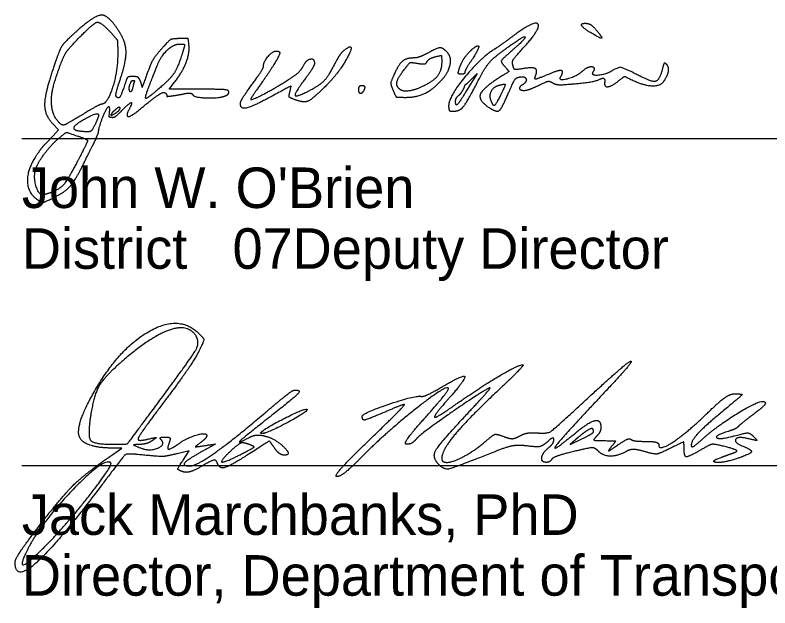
# Model space of a CAD drawing. Extents: x -1.1 to 34, y 0 to 29.8.
# Drawn here: x 24.632 to 27.241, y 6.685 to 8.733 of the extents above; entities that cross this region are included whole.
import ezdxf

# ---------------------------------------------------------------- set-up
doc = ezdxf.new("R2010")
doc.units = 0
doc.layers.add('SH_Data', color=7, linetype='Continuous')
doc.layers.add('SH_Text', color=7, linetype='Continuous')

msp = doc.modelspace()

# ---------------------------------------------------------------- linework, layer by layer
at = {"layer": 'SH_Data'}
for p, q in [((24.6551, 8.3067), (28.1551, 8.3067)), ((24.6551, 7.1773), (28.1551, 7.1773))]:
    msp.add_line(p, q, dxfattribs=at)
at = {"layer": 'SH_Text'}
for p, q in [((26.6204, 8.673), (26.6204, 8.673)), ((25.1173, 7.3823), (25.1173, 7.3823)), ((25.4827, 7.2925), (25.4827, 7.2925)), ((26.6316, 7.2945), (26.6316, 7.2945)), ((25.8545, 7.2635), (25.8545, 7.2635)), ((25.4379, 7.2508), (25.4379, 7.2508))]:
    msp.add_line(p, q, dxfattribs=at)
for points in [[(26.7632, 8.537), (26.7242, 8.5536), (26.7012, 8.5451)], [(26.1956, 8.4978), (26.229, 8.531), (26.1944, 8.4761)], [(25.2675, 8.4771), (25.1647, 8.4771), (25.183, 8.5011)], [(24.7618, 8.3577), (24.7812, 8.3371), (24.7618, 8.3153)], [(26.5799, 7.2748), (26.5504, 7.2492), (26.591, 7.2689)], [(24.9697, 7.2154), (25.0004, 7.2366), (24.9625, 7.2373)], [(25.2126, 7.1956), (25.2338, 7.2279), (25.1921, 7.2178)]]:
    msp.add_lwpolyline(points, dxfattribs=at)
for points in [[(24.9948, 8.6707), (24.9576, 8.7316), (24.9082, 8.7347), (24.8471, 8.68)], [(24.8491, 8.6511), (24.9029, 8.7064), (24.9271, 8.7109), (24.9632, 8.6723)], [(26.3801, 8.6107), (26.4497, 8.6855), (26.4295, 8.7184), (26.3504, 8.659)], [(26.6204, 8.673), (26.5942, 8.689), (26.586, 8.7053), (26.6044, 8.7049)], [(26.6044, 8.7049), (26.6159, 8.7046), (26.6335, 8.6913), (26.6494, 8.6711)], [(24.8471, 8.68), (24.8009, 8.6387), (24.7832, 8.6097), (24.7591, 8.5362)], [(24.9632, 8.6723), (24.9836, 8.6504), (24.9864, 8.6415), (24.9864, 8.5982)], [(24.9935, 8.5062), (25.0151, 8.5702), (25.0156, 8.6364), (24.9948, 8.6707)], [(26.6494, 8.6711), (26.6638, 8.6527), (26.6526, 8.6534), (26.6204, 8.673)], [(24.7866, 8.5571), (24.7992, 8.5912), (24.8172, 8.6184), (24.8491, 8.6511)], [(25.1995, 8.6521), (25.1737, 8.6513), (25.1635, 8.6454), (25.1377, 8.6163)], [(25.2328, 8.6287), (25.2306, 8.6515), (25.2284, 8.653), (25.1995, 8.6521)], [(26.2439, 8.5279), (26.2609, 8.5605), (26.3003, 8.5985), (26.3604, 8.6402)], [(26.3504, 8.659), (26.3284, 8.6425), (26.2996, 8.6221), (26.2864, 8.6136)], [(26.3604, 8.6402), (26.396, 8.6648), (26.3932, 8.6487), (26.3564, 8.6167)], [(25.1377, 8.6163), (25.1208, 8.5972), (25.1032, 8.5716), (25.0986, 8.5593)], [(25.1227, 8.5582), (25.1352, 8.5904), (25.1792, 8.6331), (25.1998, 8.6331)], [(25.214, 8.6151), (25.1971, 8.5593), (25.1726, 8.5174), (25.1402, 8.4888)], [(25.183, 8.5011), (25.2105, 8.5373), (25.2355, 8.6012), (25.2328, 8.6287)], [(25.1998, 8.6331), (25.2165, 8.6331), (25.2187, 8.6304), (25.214, 8.6151)], [(25.7671, 8.6097), (25.81, 8.6453), (25.7561, 8.5389), (25.7059, 8.4887)], [(26.1248, 8.6055), (26.1092, 8.6212), (26.0917, 8.6201), (26.0563, 8.6011)], [(26.2864, 8.6136), (26.2365, 8.5816), (26.1304, 8.4497), (26.1304, 8.4197)], [(26.1669, 8.5471), (26.1734, 8.5679), (26.1964, 8.6021), (26.2133, 8.6162)], [(26.2133, 8.6162), (26.2353, 8.6344), (26.2333, 8.6125), (26.2098, 8.5776)], [(26.3564, 8.6167), (26.3151, 8.5808), (26.3104, 8.5708), (26.3264, 8.5532)], [(24.9864, 8.5982), (24.9864, 8.5383), (24.9497, 8.4251), (24.9302, 8.4251)], [(25.5464, 8.6019), (25.5464, 8.5941), (25.5058, 8.5292), (25.467, 8.4751)], [(25.4904, 8.5571), (25.4904, 8.5721), (25.5221, 8.6091), (25.535, 8.6091)], [(25.535, 8.6091), (25.5413, 8.6091), (25.5464, 8.6059), (25.5464, 8.6019)], [(25.7382, 8.5666), (25.7477, 8.585), (25.7607, 8.6044), (25.7671, 8.6097)], [(26.0102, 8.5851), (25.9842, 8.5851), (25.9578, 8.5633), (25.9425, 8.5292)], [(26.0563, 8.6011), (26.0399, 8.5923), (26.0191, 8.5851), (26.0102, 8.5851)], [(26.0563, 8.573), (26.0597, 8.579), (26.0723, 8.5863), (26.0844, 8.5893)], [(26.0844, 8.5893), (26.1048, 8.5944), (26.1064, 8.593), (26.1064, 8.5706)], [(26.1058, 8.5085), (26.13, 8.5342), (26.1409, 8.5895), (26.1248, 8.6055)], [(26.3524, 8.5599), (26.3494, 8.5716), (26.3573, 8.5862), (26.3801, 8.6107)], [(25.0986, 8.5593), (25.0699, 8.4818), (25.0721, 8.4855), (25.0652, 8.504)], [(25.6279, 8.5571), (25.6373, 8.5779), (25.6664, 8.585), (25.6664, 8.5666)], [(25.6664, 8.5666), (25.6664, 8.5607), (25.652, 8.5367), (25.6343, 8.513)], [(25.6475, 8.4717), (25.6856, 8.4913), (25.7156, 8.5227), (25.7382, 8.5666)], [(25.9755, 8.5432), (25.994, 8.5675), (25.9998, 8.5703), (26.0234, 8.5665)], [(26.0234, 8.5665), (26.0414, 8.5636), (26.0522, 8.5657), (26.0563, 8.573)], [(26.1064, 8.5706), (26.1064, 8.5411), (26.0769, 8.5039), (26.0393, 8.4861)], [(26.2098, 8.5776), (26.1969, 8.5584), (26.1864, 8.5396), (26.1864, 8.5359)], [(26.3856, 8.548), (26.3611, 8.5441), (26.3561, 8.5459), (26.3524, 8.5599)], [(26.8839, 8.5629), (26.8778, 8.5689), (26.8736, 8.5647), (26.8696, 8.5483)], [(26.8748, 8.5051), (26.8883, 8.526), (26.8927, 8.554), (26.8839, 8.5629)], [(24.7591, 8.5362), (24.7331, 8.4569), (24.7342, 8.3872), (24.7618, 8.3577)], [(24.76, 8.4077), (24.7544, 8.437), (24.7656, 8.4997), (24.7866, 8.5571)], [(25.0993, 8.4991), (25.1085, 8.5222), (25.119, 8.5488), (25.1227, 8.5582)], [(25.4504, 8.4931), (25.4724, 8.5229), (25.4904, 8.5517), (25.4904, 8.5571)], [(25.5766, 8.5102), (25.5998, 8.525), (25.6229, 8.5461), (25.6279, 8.5571)], [(25.9597, 8.4784), (25.9486, 8.4896), (25.9552, 8.5166), (25.9755, 8.5432)], [(26.1739, 8.5291), (26.1645, 8.5291), (26.1628, 8.5337), (26.1669, 8.5471)], [(26.1864, 8.5359), (26.1864, 8.5322), (26.1808, 8.5291), (26.1739, 8.5291)], [(26.3264, 8.5532), (26.339, 8.5392), (26.3385, 8.5376), (26.3171, 8.5243)], [(26.4316, 8.5254), (26.4388, 8.5441), (26.4197, 8.5534), (26.3856, 8.548)], [(26.4882, 8.5336), (26.4363, 8.5124), (26.426, 8.5109), (26.4316, 8.5254)], [(26.5177, 8.52), (26.5286, 8.5377), (26.5144, 8.5443), (26.4882, 8.5336)], [(26.592, 8.5388), (26.5725, 8.5206), (26.508, 8.5043), (26.5177, 8.52)], [(26.6304, 8.5372), (26.6406, 8.5536), (26.6093, 8.5549), (26.592, 8.5388)], [(26.7012, 8.5451), (26.6797, 8.5287), (26.6213, 8.5224), (26.6304, 8.5372)], [(26.8696, 8.5483), (26.8591, 8.5054), (26.828, 8.5021), (26.7632, 8.537)], [(25.0393, 8.5211), (25.0236, 8.5211), (25.0177, 8.515), (25.0101, 8.4911)], [(25.0334, 8.5051), (25.0469, 8.5117), (25.0402, 8.4926), (25.039, 8.4848)], [(25.0652, 8.504), (25.0611, 8.5151), (25.052, 8.5211), (25.0393, 8.5211)], [(25.4468, 8.4411), (25.455, 8.4411), (25.5353, 8.4838), (25.5766, 8.5102)], [(25.6343, 8.513), (25.5972, 8.4632), (25.6019, 8.4483), (25.6475, 8.4717)], [(25.9425, 8.5292), (25.9304, 8.5024), (25.9297, 8.494), (25.9383, 8.4734)], [(25.9824, 8.4491), (26.0198, 8.4491), (26.075, 8.4757), (26.1058, 8.5085)], [(26.145, 8.4011), (26.1696, 8.4011), (26.1947, 8.4333), (26.2439, 8.5279)], [(26.3171, 8.5243), (26.2496, 8.4824), (26.2313, 8.4394), (26.2701, 8.414)], [(26.3352, 8.4592), (26.3537, 8.5026), (26.3643, 8.5178), (26.3772, 8.5197)], [(26.3772, 8.5197), (26.3951, 8.5223), (26.4019, 8.5027), (26.3864, 8.4931)], [(26.5835, 8.4976), (26.6355, 8.5025), (26.6741, 8.5221), (26.6691, 8.4972)], [(26.7172, 8.5056), (26.7376, 8.5216), (26.7387, 8.5217), (26.7682, 8.5076)], [(26.7682, 8.5076), (26.8056, 8.4898), (26.8639, 8.4884), (26.8748, 8.5051)], [(24.9817, 8.4512), (24.9789, 8.454), (24.9842, 8.4787), (24.9935, 8.5062)], [(25.0101, 8.4911), (24.9994, 8.4578), (24.9893, 8.4436), (24.9817, 8.4512)], [(25.0264, 8.4806), (25.0264, 8.4848), (25.027, 8.4904), (25.0334, 8.5051)], [(25.039, 8.4848), (25.035, 8.4675), (25.0264, 8.4691), (25.0264, 8.4806)], [(25.1402, 8.4888), (25.0892, 8.444), (25.0785, 8.4467), (25.0993, 8.4991)], [(25.4104, 8.428), (25.4104, 8.434), (25.4284, 8.4633), (25.4504, 8.4931)], [(25.5818, 8.4694), (25.5866, 8.4889), (25.585, 8.4885), (25.5199, 8.4533)], [(25.7059, 8.4887), (25.66, 8.4429), (25.6295, 8.4293), (25.599, 8.4409)], [(25.8311, 8.4891), (25.8241, 8.4891), (25.8184, 8.4834), (25.8184, 8.4764)], [(25.8406, 8.4796), (25.8423, 8.4848), (25.838, 8.4891), (25.8311, 8.4891)], [(26.0393, 8.4861), (26.0114, 8.4729), (25.9694, 8.4688), (25.9597, 8.4784)], [(26.1817, 8.4772), (26.1855, 8.4839), (26.1862, 8.4927), (26.1956, 8.4978)], [(26.2771, 8.4376), (26.2701, 8.4558), (26.2864, 8.4862), (26.3057, 8.4912)], [(26.3057, 8.4912), (26.326, 8.4966), (26.3265, 8.49), (26.3084, 8.4536)], [(26.3864, 8.4931), (26.3738, 8.4853), (26.3771, 8.4731), (26.3919, 8.4731)], [(26.3919, 8.4731), (26.3993, 8.4731), (26.4214, 8.4809), (26.441, 8.4904)], [(26.441, 8.4904), (26.4685, 8.5037), (26.4798, 8.5056), (26.4906, 8.4989)], [(26.4906, 8.4989), (26.5003, 8.4928), (26.5282, 8.4924), (26.5835, 8.4976)], [(26.6691, 8.4972), (26.6695, 8.4839), (26.6949, 8.488), (26.7172, 8.5056)], [(25.0595, 8.4048), (25.0935, 8.4334), (25.1535, 8.4776), (25.1567, 8.4523)], [(25.1567, 8.4523), (25.1708, 8.4536), (25.1955, 8.4574), (25.2115, 8.4606)], [(25.2115, 8.4606), (25.23, 8.4644), (25.2425, 8.4634), (25.246, 8.4578)], [(25.246, 8.4578), (25.2516, 8.4486), (25.3362, 8.4457), (25.3577, 8.454)], [(25.3704, 8.468), (25.3704, 8.4743), (25.3394, 8.4771), (25.2675, 8.4771)], [(25.3577, 8.454), (25.3647, 8.4566), (25.3704, 8.4629), (25.3704, 8.468)], [(25.467, 8.4751), (25.4536, 8.4564), (25.4445, 8.4411), (25.4468, 8.4411)], [(25.599, 8.4409), (25.5804, 8.4479), (25.5776, 8.4527), (25.5818, 8.4694)], [(25.8184, 8.4764), (25.8184, 8.4623), (25.8356, 8.4648), (25.8406, 8.4796)], [(25.9383, 8.4734), (25.9473, 8.4517), (25.952, 8.4491), (25.9824, 8.4491)], [(26.1944, 8.4761), (26.1682, 8.4321), (26.1544, 8.4178), (26.1544, 8.4344)], [(26.1544, 8.4344), (26.1544, 8.4414), (26.1598, 8.4516), (26.1664, 8.4571)], [(26.1664, 8.4571), (26.173, 8.4626), (26.1784, 8.4719), (26.1817, 8.4772)], [(26.3001, 8.4012), (26.3058, 8.4013), (26.3215, 8.4274), (26.3352, 8.4592)], [(24.998, 8.4007), (25.0244, 8.4283), (25.0391, 8.4329), (25.0267, 8.4096)], [(25.5199, 8.4533), (25.453, 8.417), (25.4104, 8.4072), (25.4104, 8.428)], [(26.3084, 8.4536), (26.2931, 8.4228), (26.2845, 8.4184), (26.2771, 8.4376)], [(24.7997, 8.3531), (24.7891, 8.3531), (24.7637, 8.3879), (24.76, 8.4077)], [(24.9302, 8.4251), (24.9262, 8.4251), (24.8963, 8.4089), (24.8637, 8.3891)], [(24.9192, 8.3249), (24.9222, 8.3539), (24.9632, 8.4433), (24.9555, 8.3826)], [(24.9681, 8.3962), (24.9708, 8.4), (24.9754, 8.404), (24.9816, 8.4091)], [(24.9816, 8.4091), (24.9918, 8.4194), (24.995, 8.4085), (24.9874, 8.4005)], [(25.0267, 8.4096), (25.0131, 8.3843), (25.0319, 8.3816), (25.0595, 8.4048)], [(26.1304, 8.4197), (26.1304, 8.407), (26.1351, 8.4011), (26.145, 8.4011)], [(26.2701, 8.414), (26.281, 8.4069), (26.2945, 8.4012), (26.3001, 8.4012)], [(24.8637, 8.3891), (24.8311, 8.3693), (24.8023, 8.3531), (24.7997, 8.3531)], [(24.8361, 8.3463), (24.8396, 8.3568), (24.9132, 8.397), (24.9187, 8.3914)], [(24.9187, 8.3914), (24.9211, 8.389), (24.9169, 8.374), (24.9093, 8.3581)], [(24.9555, 8.3826), (24.969, 8.3777), (24.984, 8.3861), (24.998, 8.4007)], [(24.9874, 8.4005), (24.9731, 8.3898), (24.9602, 8.3844), (24.9681, 8.3962)], [(24.9093, 8.3581), (24.8996, 8.3378), (24.8905, 8.3294), (24.8789, 8.33)], [(24.7866, 8.3109), (24.8078, 8.3282), (24.8097, 8.3284), (24.8455, 8.3162)], [(24.8789, 8.33), (24.8505, 8.3316), (24.8334, 8.3381), (24.8361, 8.3463)], [(24.9064, 8.2964), (24.91, 8.3015), (24.913, 8.312), (24.9192, 8.3249)], [(24.7017, 8.197), (24.7073, 8.2197), (24.7581, 8.2878), (24.7866, 8.3109)], [(24.7618, 8.3153), (24.7511, 8.3034), (24.7384, 8.2899), (24.7334, 8.2853)], [(24.8455, 8.3162), (24.8658, 8.3093), (24.8824, 8.3018), (24.8824, 8.2996)], [(24.8824, 8.2996), (24.8824, 8.2974), (24.8677, 8.2673), (24.8497, 8.2327)], [(24.7334, 8.2853), (24.7285, 8.2808), (24.715, 8.2628), (24.7034, 8.2453)], [(24.8763, 8.2358), (24.889, 8.2627), (24.9034, 8.2895), (24.9064, 8.2964)], [(24.7034, 8.2453), (24.6725, 8.1984), (24.6758, 8.1178), (24.7096, 8.0952)], [(24.8497, 8.2327), (24.8152, 8.1663), (24.7864, 8.1318), (24.7559, 8.1202)], [(24.7698, 8.1048), (24.8075, 8.124), (24.8456, 8.171), (24.8763, 8.2358)], [(24.7262, 8.1131), (24.7127, 8.1131), (24.6954, 8.1721), (24.7017, 8.197)], [(24.7559, 8.1202), (24.7457, 8.1163), (24.7323, 8.1131), (24.7262, 8.1131)], [(24.7096, 8.0952), (24.7236, 8.0859), (24.7369, 8.088), (24.7698, 8.1048)], [(24.906, 7.4331), (24.9923, 7.5835), (25.2004, 7.6995), (25.2661, 7.6339)], [(25.2571, 7.6247), (25.2311, 7.6667), (25.1051, 7.6255), (25.0097, 7.5439)], [(25.1173, 7.3823), (25.2387, 7.5458), (25.2711, 7.602), (25.2571, 7.6247)], [(25.2661, 7.6339), (25.2848, 7.6151), (25.2849, 7.61), (25.2666, 7.5716)], [(25.2666, 7.5716), (25.2556, 7.5486), (25.2039, 7.4731), (25.1516, 7.4037)], [(25.0097, 7.5439), (24.9431, 7.4869), (24.9042, 7.4228), (24.8931, 7.3515)], [(26.1598, 7.3916), (26.2403, 7.4482), (26.3716, 7.5254), (26.3873, 7.5254)], [(26.3873, 7.5254), (26.3922, 7.5254), (26.3509, 7.4828), (26.2955, 7.4307)], [(26.614, 7.412), (26.689, 7.4811), (26.7551, 7.5377), (26.7608, 7.5378)], [(26.7608, 7.5378), (26.7665, 7.5379), (26.7145, 7.4777), (26.6452, 7.4041)], [(26.1008, 7.4451), (26.1796, 7.4913), (26.1918, 7.478), (26.1326, 7.4107)], [(25.4962, 7.3596), (25.5466, 7.4025), (25.5921, 7.4376), (25.5973, 7.4378)], [(25.5973, 7.4378), (25.6221, 7.4383), (25.5988, 7.4127), (25.5129, 7.3454)], [(26.1289, 7.4449), (26.1193, 7.4545), (25.9095, 7.2875), (25.8316, 7.2083)], [(26.2691, 7.4444), (26.2201, 7.4166), (26.0318, 7.2844), (26.0185, 7.2685)], [(26.0352, 7.4159), (26.0407, 7.414), (26.0703, 7.4272), (26.1008, 7.4451)], [(26.0511, 7.3445), (26.0974, 7.3962), (26.1324, 7.4414), (26.1289, 7.4449)], [(26.204, 7.3655), (26.2501, 7.4147), (26.2795, 7.4502), (26.2691, 7.4444)], [(24.9625, 7.2373), (24.8646, 7.239), (24.8412, 7.3201), (24.906, 7.4331)], [(25.8318, 7.3473), (25.8321, 7.3579), (26.0194, 7.421), (26.0352, 7.4159)], [(26.1326, 7.4107), (26.1046, 7.3789), (26.0816, 7.3492), (26.0816, 7.3448)], [(26.2955, 7.4307), (26.1959, 7.337), (26.1066, 7.2289), (26.1066, 7.2019)], [(26.439, 7.2896), (26.4725, 7.2868), (26.496, 7.3032), (26.614, 7.412)], [(27.0223, 7.3558), (27.0675, 7.3995), (27.1046, 7.4252), (27.1223, 7.4249)], [(27.1223, 7.4249), (27.1466, 7.4244), (27.1428, 7.418), (27.0941, 7.378)], [(25.1516, 7.4037), (25.0994, 7.3344), (25.0566, 7.2737), (25.0566, 7.2689)], [(25.8545, 7.2635), (25.9255, 7.3319), (25.9808, 7.3879), (25.9774, 7.3879)], [(25.9774, 7.3879), (25.974, 7.3879), (25.945, 7.3767), (25.9129, 7.3629)], [(26.0816, 7.3448), (26.0816, 7.3403), (26.1168, 7.3614), (26.1598, 7.3916)], [(26.6452, 7.4041), (26.5156, 7.2666), (26.4836, 7.2193), (26.5657, 7.287)], [(27.0035, 7.2646), (27.0571, 7.3134), (27.2041, 7.4034), (27.221, 7.3977)], [(27.221, 7.3977), (27.2294, 7.3949), (27.2141, 7.3762), (27.187, 7.356)], [(24.9712, 7.2504), (25.0179, 7.2504), (25.0224, 7.2545), (25.1173, 7.3823)], [(25.2348, 7.1754), (25.2579, 7.1754), (25.3839, 7.2642), (25.4962, 7.3596)], [(25.4827, 7.2925), (25.5031, 7.3104), (25.6351, 7.3761), (25.6403, 7.371)], [(25.6403, 7.371), (25.6464, 7.3648), (25.5038, 7.2879), (25.4862, 7.2879)], [(25.9129, 7.3629), (25.8503, 7.3361), (25.8315, 7.3325), (25.8318, 7.3473)], [(26.0969, 7.1798), (26.0717, 7.2051), (26.1006, 7.2552), (26.204, 7.3655)], [(27.0941, 7.378), (27.0201, 7.3171), (26.9691, 7.2635), (26.9691, 7.2468)], [(24.8931, 7.3515), (24.8817, 7.2782), (24.9031, 7.2504), (24.9712, 7.2504)], [(25.5129, 7.3454), (25.4197, 7.2724), (25.3982, 7.2509), (25.4421, 7.2744)], [(25.9852, 7.2504), (25.9749, 7.2504), (26.0038, 7.2917), (26.0511, 7.3445)], [(26.5657, 7.287), (26.6141, 7.3269), (26.6566, 7.3373), (26.6566, 7.3092)], [(26.8566, 7.2489), (26.8566, 7.2261), (26.9519, 7.2875), (27.0223, 7.3558)], [(27.187, 7.356), (27.16, 7.3358), (27.1351, 7.3158), (27.1316, 7.3116)], [(26.6566, 7.3092), (26.6566, 7.3003), (26.6499, 7.2862), (26.6416, 7.2779)], [(27.1316, 7.3116), (27.1282, 7.3073), (27.1127, 7.2999), (27.0973, 7.295)], [(25.2007, 7.2548), (25.2296, 7.2746), (25.2941, 7.2921), (25.2941, 7.2802)], [(25.2941, 7.2802), (25.2941, 7.2757), (25.2844, 7.2648), (25.2725, 7.2561)], [(25.4421, 7.2744), (25.4548, 7.2811), (25.4787, 7.2832), (25.4952, 7.279)], [(25.4862, 7.2879), (25.4814, 7.2879), (25.4798, 7.29), (25.4827, 7.2925)], [(26.2641, 7.2655), (26.2844, 7.2835), (26.2973, 7.2861), (26.321, 7.2771)], [(26.376, 7.2792), (26.3894, 7.2867), (26.4178, 7.2914), (26.439, 7.2896)], [(26.6316, 7.2945), (26.6316, 7.308), (26.6076, 7.2988), (26.5799, 7.2748)], [(26.591, 7.2689), (26.6134, 7.2797), (26.6316, 7.2912), (26.6316, 7.2945)], [(27.0973, 7.295), (27.0477, 7.2796), (27.0672, 7.2659), (27.1191, 7.2797)], [(27.1191, 7.2797), (27.1574, 7.29), (27.1727, 7.2894), (27.1847, 7.2771)], [(25.0566, 7.2689), (25.0566, 7.2641), (25.0721, 7.2638), (25.091, 7.2682)], [(25.1066, 7.2635), (25.0963, 7.2565), (25.0766, 7.2504), (25.0629, 7.2498)], [(25.0671, 7.2372), (25.0969, 7.2252), (25.1532, 7.2498), (25.1357, 7.2672)], [(25.091, 7.2682), (25.1165, 7.2741), (25.1206, 7.2729), (25.1066, 7.2635)], [(25.1357, 7.2672), (25.1312, 7.2717), (25.1375, 7.2754), (25.1496, 7.2754)], [(25.1496, 7.2754), (25.1642, 7.2754), (25.1694, 7.269), (25.1646, 7.2567)], [(25.1646, 7.2567), (25.1557, 7.2334), (25.1685, 7.2328), (25.2007, 7.2548)], [(25.2725, 7.2561), (25.2536, 7.2423), (25.2556, 7.241), (25.2881, 7.2459)], [(25.4379, 7.2508), (25.4207, 7.2572), (25.4042, 7.252), (25.3848, 7.2343)], [(25.5283, 7.2376), (25.5114, 7.2617), (25.5094, 7.2612), (25.4436, 7.2189)], [(25.4952, 7.279), (25.5313, 7.2699), (25.5897, 7.2129), (25.563, 7.2129)], [(25.7441, 7.1386), (25.7338, 7.1388), (25.7835, 7.195), (25.8545, 7.2635)], [(26.0185, 7.2685), (26.0103, 7.2585), (25.9953, 7.2504), (25.9852, 7.2504)], [(26.1247, 7.1879), (26.1464, 7.1879), (26.2277, 7.2332), (26.2641, 7.2655)], [(26.321, 7.2771), (26.3412, 7.2694), (26.36, 7.2701), (26.376, 7.2792)], [(26.4716, 7.2589), (26.4559, 7.2447), (26.4347, 7.2403), (26.4021, 7.2445)], [(26.4941, 7.2664), (26.4941, 7.2735), (26.484, 7.2701), (26.4716, 7.2589)], [(26.4754, 7.2379), (26.4857, 7.2465), (26.4941, 7.2593), (26.4941, 7.2664)], [(26.6416, 7.2779), (26.63, 7.2663), (26.6359, 7.2629), (26.6682, 7.2629)], [(26.6682, 7.2629), (26.7057, 7.2629), (26.7081, 7.2609), (26.6925, 7.2416)], [(26.7143, 7.2474), (26.7357, 7.2624), (26.7564, 7.2715), (26.7603, 7.2676)], [(26.7603, 7.2676), (26.7643, 7.2636), (26.7875, 7.2604), (26.8121, 7.2604)], [(26.8121, 7.2604), (26.8366, 7.2604), (26.8566, 7.2553), (26.8566, 7.2489)], [(26.9441, 7.2364), (26.9441, 7.2593), (26.9431, 7.2593), (26.8969, 7.2364)], [(26.9691, 7.2468), (26.9691, 7.2393), (26.9846, 7.2473), (27.0035, 7.2646)], [(27.166, 7.2697), (27.1293, 7.2787), (27.116, 7.2556), (27.1504, 7.2425)], [(27.1847, 7.2771), (27.1974, 7.2642), (27.1938, 7.2628), (27.166, 7.2697)], [(25.0629, 7.2498), (25.0405, 7.249), (25.0409, 7.2476), (25.0671, 7.2372)], [(25.2881, 7.2459), (25.3249, 7.2515), (25.3248, 7.2512), (25.2793, 7.2261)], [(25.3848, 7.2343), (25.3405, 7.1938), (25.3518, 7.1849), (25.4098, 7.2145)], [(25.4098, 7.2145), (25.4561, 7.2382), (25.4597, 7.2428), (25.4379, 7.2508)], [(25.563, 7.2129), (25.5534, 7.2129), (25.5378, 7.224), (25.5283, 7.2376)], [(26.4021, 7.2445), (26.3728, 7.2482), (26.333, 7.2417), (26.2965, 7.2273)], [(26.4684, 7.1879), (26.45, 7.1879), (26.4546, 7.2207), (26.4754, 7.2379)], [(26.647, 7.2275), (26.6359, 7.2387), (26.6159, 7.2382), (26.5627, 7.2254)], [(26.6925, 7.2416), (26.6805, 7.2266), (26.687, 7.2283), (26.7143, 7.2474)], [(26.8078, 7.2251), (26.781, 7.2328), (26.7579, 7.2328), (26.7434, 7.225)], [(26.8969, 7.2364), (26.8595, 7.2179), (26.841, 7.2156), (26.8078, 7.2251)], [(27.0061, 7.2333), (26.961, 7.2067), (26.9441, 7.2076), (26.9441, 7.2364)], [(27.0893, 7.2414), (27.0504, 7.2513), (27.0337, 7.2496), (27.0061, 7.2333)], [(27.1191, 7.2222), (27.1305, 7.2263), (27.1188, 7.2338), (27.0893, 7.2414)], [(27.1504, 7.2425), (27.1809, 7.2307), (27.172, 7.2158), (27.1253, 7.2004)], [(24.7188, 6.9732), (24.7964, 7.0737), (24.8765, 7.151), (24.9697, 7.2154)], [(25.0509, 7.2155), (25.0175, 7.2188), (25.0058, 7.2083), (24.9291, 7.1067)], [(25.1921, 7.2178), (25.1518, 7.2081), (25.1294, 7.2077), (25.0509, 7.2155)], [(25.2793, 7.2261), (25.2283, 7.1979), (25.2085, 7.1754), (25.2348, 7.1754)], [(25.4436, 7.2189), (25.3748, 7.1745), (25.3373, 7.1648), (25.3292, 7.1891)], [(25.8316, 7.2083), (25.7938, 7.1698), (25.7545, 7.1384), (25.7441, 7.1386)], [(26.2965, 7.2273), (26.1504, 7.1696), (26.1154, 7.1613), (26.0969, 7.1798)], [(26.1066, 7.2019), (26.1066, 7.1942), (26.1148, 7.1879), (26.1247, 7.1879)], [(26.5627, 7.2254), (26.5244, 7.2162), (26.4901, 7.204), (26.4866, 7.1983)], [(26.7434, 7.225), (26.7126, 7.2086), (26.6648, 7.2098), (26.647, 7.2275)], [(27.1253, 7.2004), (27.0787, 7.185), (27.0313, 7.1907), (27.0754, 7.2064)], [(27.0754, 7.2064), (27.0891, 7.2113), (27.1088, 7.2184), (27.1191, 7.2222)], [(24.9626, 7.1862), (24.9417, 7.2071), (24.7231, 6.9814), (24.6768, 6.8911)], [(24.7469, 6.9098), (24.8145, 6.9789), (24.9703, 7.1785), (24.9626, 7.1862)], [(25.2114, 7.1555), (25.1933, 7.1625), (25.1934, 7.1661), (25.2126, 7.1956)], [(25.3292, 7.1891), (25.3263, 7.1977), (25.3071, 7.1925), (25.278, 7.1753)], [(26.4866, 7.1983), (26.483, 7.1926), (26.4749, 7.1879), (26.4684, 7.1879)], [(25.278, 7.1753), (25.2524, 7.1602), (25.2224, 7.1513), (25.2114, 7.1555)], [(24.9291, 7.1067), (24.7767, 6.9046), (24.6316, 6.776), (24.6316, 6.843)], [(24.6316, 6.843), (24.6316, 6.8526), (24.6709, 6.9112), (24.7188, 6.9732)], [(24.6768, 6.8911), (24.6456, 6.8301), (24.6772, 6.8386), (24.7469, 6.9098)]]:
    msp.add_open_spline(points, degree=2, dxfattribs=at)

# ---------------------------------------------------------------- texts
for s, p in [("John W. O'Brien", (24.6551, 8.0667)), ('District       Deputy Director', (24.6551, 7.8567)), ('              07', (24.6551, 7.8567)), ('Jack Marchbanks, PhD', (24.6551, 6.9373)), ('Director, Department of Transportation', (24.6551, 6.7273))]:
    msp.add_text(s, height=0.14, dxfattribs=at).set_placement(p)

doc.saveas('drawing.dxf')
